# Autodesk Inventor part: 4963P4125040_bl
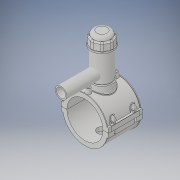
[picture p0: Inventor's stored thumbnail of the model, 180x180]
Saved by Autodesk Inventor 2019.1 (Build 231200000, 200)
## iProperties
Created: 2017-07
Part Number: 4963P4125040_bl
Material: Generic
Document SubType Name: Modeling
Designer: KIM
Density: 1 g/cm^3
Appearance: Default
Author: KIM
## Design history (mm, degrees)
derived "4963P4.ipt"
feature "Solid1::4963P4.ipt" dims "ScaleForDerivedMember" = 10
feature "Solid2::4963P4.ipt" dims "ScaleForDerivedMember" = 10
feature "Solid3::4963P4.ipt" dims "ScaleForDerivedMember" = 10
tag "TaggingFeature1"
body "Solid1"
body "Solid2"
body "Solid3"
other parameters: "d0" = 125 [user parameter], "d2" = 162 [user parameter], "d3" = 31.25 [user parameter], "d4" = 118 [user parameter], "d5" = 0 [user parameter], "d6" = 0.1 [user parameter], "d8" = 0 [user parameter], "d19" = 6 [user parameter], "d20" = 6 [user parameter], "d21" = 70.8 [user parameter], "d23" = 0 [user parameter], "d24" = 35.4 [user parameter], "d26" = 0 [user parameter], "d27" = 3 [user parameter], "d28" = 3 [user parameter], "d29" = 3 [user parameter], "d30" = 41.66667 [user parameter], "d31" = 6 [user parameter], "d32" = 0 [user parameter], "d33" = 0 [user parameter], "d34" = 0.6 [user parameter], "d40" = 79.3 [user parameter], "d41" = 75 [user parameter], "d43" = 0 [user parameter], "d45" = 0 [user parameter], "d47" = 147.05 [user parameter], "d70" = 15 [user parameter], "d72" = 0 [user parameter], "d73" = 6 [user parameter], "d75" = 5 [user parameter], "d76" = 0 [user parameter], "d77" = 6.25 [user parameter], "d78" = 92.5 [user parameter], "d79" = 15 [user parameter], "d80" = 47.2 [user parameter], "d82" = 5 deg [user parameter], "d84" = 4 [user parameter], "d85" = 14 [user parameter], "d86" = 0 [user parameter], "d87" = 3 [user parameter], "d88" = 0 [user parameter], "d89" = 1 [user parameter], "d90" = 1 [user parameter], "d91" = 94.4 [user parameter], "d92" = 0 [user parameter], "d93" = 0.5 [user parameter], "d94" = 65.78947 [user parameter], "d96" = 155.55 [user parameter], "d97" = 2.36 [user parameter], "d98" = 0 [user parameter], "d102" = 1.25 [user parameter], "d120" = 140 deg [user parameter], "d121" = 24.228 [user parameter], "d122" = 20 deg [user parameter], "d123" = 305 [user parameter], "d124" = 91.5 [user parameter], "d126" = 0 [user parameter], "d143" = 128.75 [user parameter], "d145" = 21.15385 [user parameter], "d149" = 1.875 [user parameter], "d150" = 23.26923 [user parameter], "d153" = 118 [user parameter], "d154" = 0 [user parameter], "d156" = 76.25 [user parameter], "d157" = 160 deg [user parameter], "d159" = 5.5 [user parameter], "d161" = 1.875 [user parameter], "d162" = 70.8 [user parameter], "d163" = 0 [user parameter], "d164" = 62.5 [user parameter], "d167" = 12.5 [user parameter], "d168" = 74.39024 [user parameter], "d170" = 3.75 [user parameter], "d172" = 0 [user parameter], "d173" = 1 [user parameter], "d175" = 62.5 [user parameter], "d176" = 20 deg [user parameter], "d177" = 8.75 [user parameter], "d178" = 27.5 [user parameter], "d180" = 0 [user parameter], "d183" = 11 [user parameter], "d184" = 7 [user parameter], "d185" = 38.35 [user parameter], "d186" = 38.35 [user parameter], "d187" = 76.25 [user parameter], "d188" = 8.25 [user parameter], "d189" = 8.75 [user parameter], "d190" = 0 [user parameter], "d191" = 114.375 [user parameter], "d193" = 8 [user parameter], "d194" = 4.13 [user parameter], "d195" = 90 deg [user parameter], "d197" = 0 [user parameter], "d199" = 0 [user parameter], "d200" = 13.75 [user parameter], "d202" = 0 [user parameter], "d203" = 177 [user parameter], "d204" = 71.25 [user parameter], "d205" = 52.5 [user parameter], "d206" = 63.75 [user parameter], "d207" = 132.75 [user parameter], "d208" = 138.06 [user parameter], "d209" = 164.61 [user parameter], "d210" = 64.5 [user parameter], "d211" = 75 [user parameter], "d213" = 36 [user parameter], "d216" = 0 [user parameter], "d217" = 12.5 [user parameter], "d218" = 12.5 [user parameter], "d219" = 2.5 [user parameter], "d222" = 125 [user parameter], "d224" = 0 [user parameter], "d227" = 32 [user parameter], "d228" = 142 [user parameter], "d230" = 5 [user parameter], "d_" = 125 [user parameter], "B_" = 162 [user parameter], "L_" = 118 [user parameter], "d_t" = 6 [user parameter], "H_2" = 177 [user parameter]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
